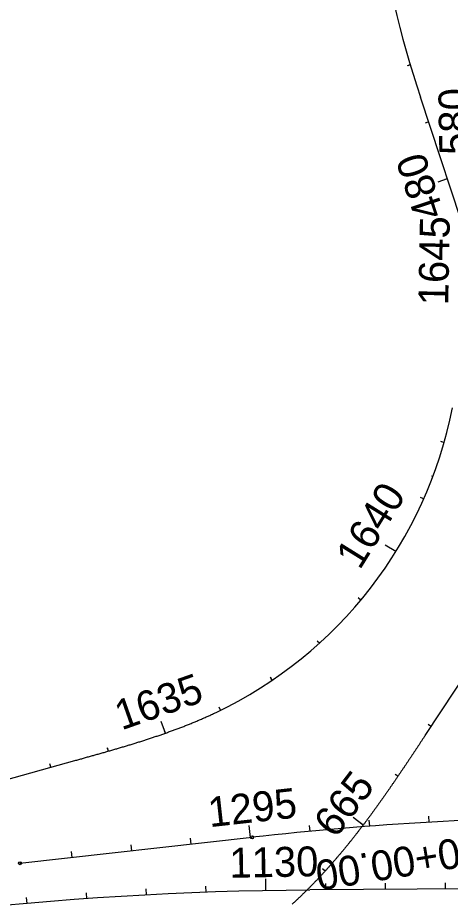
# Model space of a CAD drawing. Extents: x 448091 to 665917, y 1461380 to 1587607.
# Drawn here: x 475956 to 476679, y 1531828 to 1533309 of the extents above; entities that cross this region are included whole.
import ezdxf

# ---------------------------------------------------------------- set-up
doc = ezdxf.new("R2010")
doc.units = 0
for name, color, linetype in [('Attenuator_ep', 7, 'Continuous'), ('ATVHP', 7, 'Continuous'), ('TextShtNo', 7, 'Continuous'), ('TextTitle', 7, 'Continuous')]:
    doc.layers.add(name, color=color, linetype=linetype)

msp = doc.modelspace()

# ---------------------------------------------------------------- linework, layer by layer
at = {"layer": 'Attenuator_ep'}
msp.add_circle((475959.2, 1531896.6), 2.5, dxfattribs=at)
at = {"layer": 'ATVHP'}
msp.add_circle((476347.3, 1531939.9), 2.5, dxfattribs=at)
at = {"layer": 'TextShtNo'}
for p, q in [((475959.2, 1531896.6), (476347.3, 1531939.9)), ((480432.9, 1531875.4), (476443.8, 1531852.3))]:
    msp.add_line(p, q, dxfattribs=at)
for centre, end in [((476982.4, 1526245.6), 96.3633), ((476476.9, 1526122.2), 102.9478)]:
    msp.add_arc(centre, 5729.6, 90.3311, end, dxfattribs=at)
at = {"layer": 'TextTitle'}
for p, q in [((476611.9, 1533229.8), (476606.4, 1533228.2)), ((476611.9, 1533229.8), (476607.8, 1533228.6)), ((476878.8, 1532416.7), (476628.8, 1533176)), ((476642.4, 1533134.6), (476637, 1533132.8)), ((476642.4, 1533134.6), (476638.3, 1533133.3)), ((476673.7, 1533039.6), (476657.7, 1533034.3)), ((476673.7, 1533039.6), (476669.6, 1533038.3)), ((476668.2, 1532599.3), (476662.7, 1532600.9)), ((476668.2, 1532599.3), (476664.1, 1532600.5)), ((476649.4, 1532542.4), (476647.3, 1532543.2)), ((476634.3, 1532505.3), (476629, 1532507.7)), ((476634.3, 1532505.3), (476630.3, 1532507.1)), ((476636.6, 1532109.8), (476902.4, 1532511.3)), ((476587.6, 1532417), (476569.9, 1532428)), ((476587.6, 1532417), (476583.9, 1532419.3)), ((476529, 1532336), (476524.6, 1532339.7)), ((476529, 1532336), (476525.7, 1532338.8)), ((476459.8, 1532264), (476455.9, 1532268.3)), ((476459.8, 1532264), (476456.9, 1532267.2)), ((476381.2, 1532202.3), (476377.9, 1532207.1)), ((476381.2, 1532202.3), (476378.7, 1532205.9)), ((476294.7, 1532152.2), (476292.2, 1532157.3)), ((476294.7, 1532152.2), (476292.8, 1532156)), ((476202.4, 1532113.9), (476195.5, 1532133.4)), ((476646.6, 1532124.9), (476641.8, 1532128.1)), ((476646.6, 1532124.9), (476643, 1532127.3)), ((476202.4, 1532113.9), (476201, 1532117.9)), ((476107.1, 1532083.8), (476105.5, 1532089.4)), ((476107.1, 1532083.8), (476105.9, 1532088)), ((475845.1, 1532011.1), (476051.1, 1532068.1)), ((476010.7, 1532057), (476009.2, 1532062.5)), ((476010.7, 1532057), (476009.6, 1532061.1)), ((476591.1, 1532041.8), (476586.4, 1532045)), ((476591.1, 1532041.8), (476587.6, 1532044.2)), ((476533, 1531960.4), (476516.5, 1531972.9)), ((476643.7, 1531965.2), (476643.1, 1531975.2)), ((476344.9, 1531939.6), (476342.6, 1531959.5)), ((476444.3, 1531949.9), (476443.4, 1531959.8)), ((476533, 1531960.4), (476529.6, 1531963)), ((476544, 1531958.4), (476543.2, 1531968.4)), ((476245.5, 1531928.5), (476244.4, 1531938.5)), ((476046.7, 1531906.4), (476045.6, 1531916.3)), ((476146.1, 1531917.5), (476145, 1531927.4)), ((476469.4, 1531883.3), (476465.1, 1531887.2)), ((476469.4, 1531883.3), (476466.2, 1531886.2)), ((476370.6, 1531850.8), (476370.3, 1531870.8)), ((476170.8, 1531843.6), (476170.2, 1531853.6)), ((476270.7, 1531848.1), (476270.3, 1531858.1)), ((476470.6, 1531852.5), (476470.6, 1531862.5)), ((476570.6, 1531853.1), (476570.6, 1531863.1)), ((476670.6, 1531853.6), (476670.6, 1531863.6)), ((475971.3, 1531829.4), (475970.4, 1531839.4)), ((476071, 1531837.4), (476070.3, 1531847.4))]:
    msp.add_line(p, q, dxfattribs=at)
for centre, radius, start, end in [((478442.9, 1533773.2), 1909.9, 188.494, 198.2241), ((475979.4, 1532795.2), 716.2, 295.4756, 348.9055)]:
    msp.add_arc(centre, radius, start, end, dxfattribs=at)
for points in [[(476051.1, 1532068.1), (476054.3, 1532069), (476057.6, 1532069.9), (476060.8, 1532070.8), (476064.1, 1532071.7), (476067.4, 1532072.7), (476070.6, 1532073.6), (476073.9, 1532074.5), (476077.1, 1532075.4), (476080.4, 1532076.3), (476083.6, 1532077.2), (476086.9, 1532078.1), (476090.1, 1532079), (476093.4, 1532079.9), (476096.6, 1532080.9), (476099.9, 1532081.8), (476103.1, 1532082.7), (476106.4, 1532083.6), (476109.6, 1532084.6), (476112.9, 1532085.5), (476116.1, 1532086.4), (476119.4, 1532087.4), (476122.6, 1532088.3), (476125.8, 1532089.3), (476129.1, 1532090.3), (476132.3, 1532091.2), (476135.6, 1532092.2), (476138.8, 1532093.2), (476142, 1532094.1), (476145.3, 1532095.1), (476148.5, 1532096.1), (476151.7, 1532097.1), (476154.9, 1532098.1), (476158.2, 1532099.1), (476161.4, 1532100.1), (476164.6, 1532101.2), (476167.8, 1532102.2), (476171, 1532103.2), (476174.2, 1532104.3), (476177.5, 1532105.3), (476180.7, 1532106.4), (476183.9, 1532107.5), (476187.1, 1532108.6), (476190.3, 1532109.6), (476193.5, 1532110.7), (476196.7, 1532111.8), (476199.8, 1532113), (476203, 1532114.1), (476206.2, 1532115.2), (476209.4, 1532116.4), (476212.6, 1532117.5), (476215.7, 1532118.7), (476218.9, 1532119.8), (476222.1, 1532121), (476225.2, 1532122.2), (476228.4, 1532123.4), (476231.5, 1532124.6), (476234.7, 1532125.9), (476237.8, 1532127.1), (476241, 1532128.4), (476244.1, 1532129.6), (476247.2, 1532130.9), (476250.4, 1532132.2), (476253.5, 1532133.5), (476256.6, 1532134.8), (476259.7, 1532136.1), (476262.8, 1532137.5), (476265.9, 1532138.8), (476269, 1532140.2), (476272.1, 1532141.5), (476275.2, 1532142.9), (476278.2, 1532144.3), (476281.3, 1532145.8), (476284.4, 1532147.2), (476287.4, 1532148.6)], [(476636.6, 1532109.8), (476633.9, 1532105.7), (476631.2, 1532101.7), (476628.5, 1532097.6), (476625.9, 1532093.6), (476623.2, 1532089.5), (476620.5, 1532085.5), (476617.8, 1532081.4), (476615.1, 1532077.4), (476612.4, 1532073.3), (476609.7, 1532069.3), (476607, 1532065.2), (476604.3, 1532061.2), (476601.6, 1532057.2), (476598.8, 1532053.1), (476596.1, 1532049.1), (476593.4, 1532045.1), (476590.6, 1532041), (476587.9, 1532037), (476585.2, 1532033), (476582.4, 1532029), (476579.6, 1532025), (476576.9, 1532021), (476574.1, 1532017), (476571.3, 1532013), (476568.5, 1532009), (476565.7, 1532005.1), (476562.9, 1532001.1), (476560.1, 1531997.1), (476557.2, 1531993.2), (476554.4, 1531989.2), (476551.5, 1531985.3), (476548.7, 1531981.4), (476545.8, 1531977.4), (476542.9, 1531973.5), (476540, 1531969.6), (476537.1, 1531965.7), (476534.1, 1531961.8), (476531.2, 1531958), (476528.2, 1531954.1), (476525.3, 1531950.2), (476522.3, 1531946.4), (476519.3, 1531942.6), (476516.3, 1531938.8), (476513.3, 1531934.9), (476510.2, 1531931.2), (476507.2, 1531927.4), (476504.1, 1531923.6), (476501, 1531919.8), (476497.9, 1531916.1), (476494.8, 1531912.4), (476491.6, 1531908.7), (476488.5, 1531905), (476485.3, 1531901.3), (476482.1, 1531897.6), (476478.9, 1531893.9), (476475.6, 1531890.3), (476472.4, 1531886.7), (476469.1, 1531883.1), (476465.8, 1531879.5), (476462.5, 1531875.9), (476459.2, 1531872.4), (476455.9, 1531868.8), (476452.5, 1531865.3), (476449.1, 1531861.8), (476445.7, 1531858.4), (476442.3, 1531854.9), (476438.8, 1531851.5), (476435.4, 1531848.1), (476431.9, 1531844.7), (476428.4, 1531841.3), (476424.8, 1531838), (476421.3, 1531834.6), (476417.7, 1531831.3), (476414.1, 1531828.1)]]:
    msp.add_spline(points, degree=3, dxfattribs=at)

# ---------------------------------------------------------------- texts
at = {"layer": 'ATVHP'}
msp.add_text('POT Sta 100+00.00', height=50, rotation=189.34, dxfattribs=at).set_placement((477035.4, 1531996.1))
at = {"layer": 'TextTitle'}
for s, rotation, p in [('580', 90.8482, (476710.4, 1533080)), ('480', 108.2241, (476669.3, 1532981)), ('1645', 88.8903, (476675.2, 1532828.1)), ('1640', 58.1273, (476527.3, 1532385.1)), ('1635', 19.4772, (476129, 1532118.2)), ('665', 52.8229, (476486.9, 1531936.4)), ('1295', 6.3633, (476276.5, 1531956.7)), ('1130', 1.0629, (476309.9, 1531872.2))]:
    msp.add_text(s, height=50, rotation=rotation, dxfattribs=at).set_placement(p)

doc.saveas('drawing.dxf')
